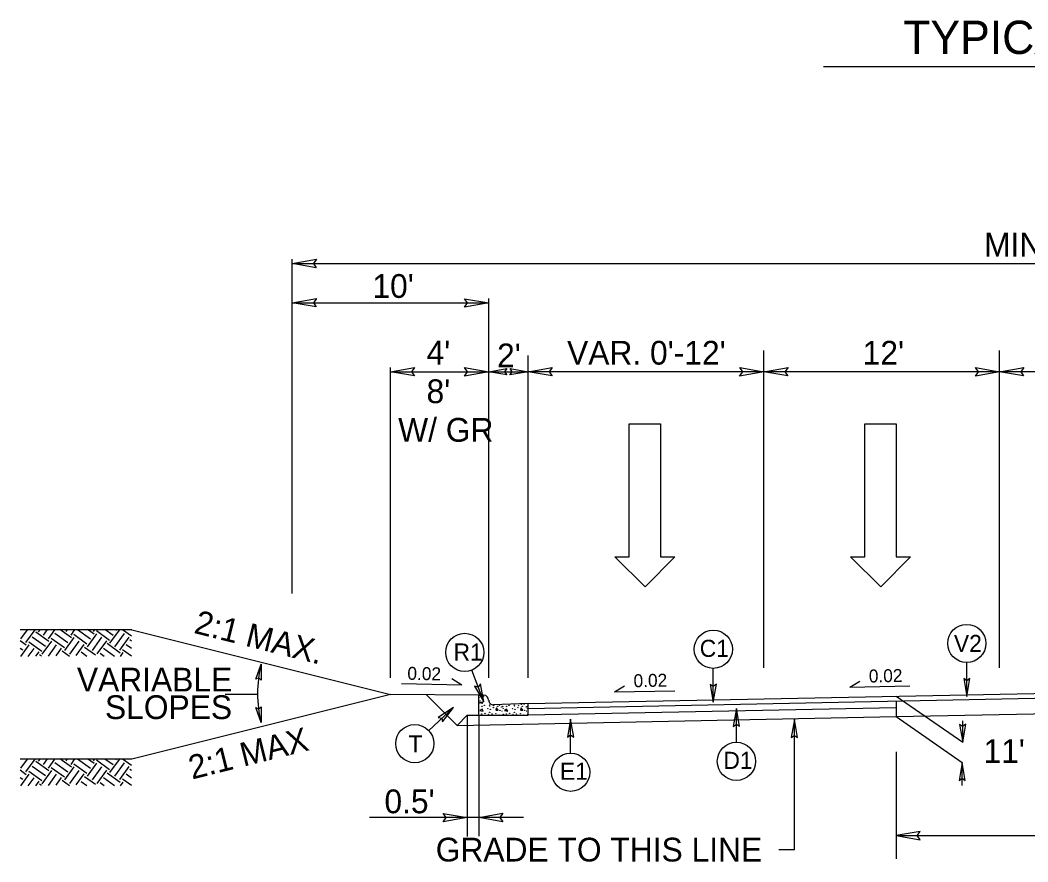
# Model space of a CAD drawing. Extents: x 3025871 to 3026431, y 707165 to 707825.
# Drawn here: x 3026115.5 to 3026166.8, y 707641 to 707683.9 of the extents above; entities that cross this region are included whole.
import ezdxf

# ---------------------------------------------------------------- set-up
doc = ezdxf.new("R2010")
doc.units = 0
for name, color, linetype in [('Prop Drainage Structure Junction Box with Manhole CELL', 7, 'Continuous'), ('Prop Drainage Structure Junction Box with Slab Lid TB 840 34 CELL', 7, 'Continuous'), ('Prop Drainage Structure Plot Symbol 50 Scale', 7, 'Continuous'), ('Prop Pavement Schedule Description CELL', 7, 'Continuous'), ('Sheet Data Field CELL', 7, 'Continuous'), ('Sheet Plot Border Inside CELL', 7, 'Continuous'), ('Sheet Sticker Incomplete CELL', 7, 'Continuous'), ('Sheet Typical CELL', 7, 'Continuous'), ('Typical Arrow Superelevation CELL', 7, 'Continuous'), ('Typical Grade Point Symbol CELL', 7, 'Continuous'), ('Typical Text Centerline CELL', 7, 'Continuous'), ('Typical Text Grade Point CELL', 7, 'Continuous')]:
    doc.layers.add(name, color=color, linetype=linetype)

msp = doc.modelspace()

# ---------------------------------------------------------------- linework, layer by layer
at = {"layer": 'Prop Drainage Structure Junction Box with Manhole CELL'}
msp.add_line((3026137.701, 707647.974), (3026160.043, 707648.421), dxfattribs=at)
at = {"layer": 'Prop Drainage Structure Junction Box with Slab Lid TB 840 34 CELL'}
for p, q in [((3026156.341, 707681.503), (3026191.781, 707681.503)), ((3026129.305, 707654.691), (3026129.305, 707671.691)), ((3026129.305, 707671.473), (3026223.819, 707671.473)), ((3026129.305, 707669.473), (3026139.305, 707669.473)), ((3026139.305, 707650.399), (3026139.305, 707669.691)), ((3026153.311, 707650.898), (3026153.311, 707667.04)), ((3026165.311, 707650.898), (3026165.311, 707667.04)), ((3026141.311, 707650.658), (3026141.311, 707666.8)), ((3026134.305, 707650.399), (3026134.305, 707666.185)), ((3026134.305, 707665.967), (3026139.305, 707665.967)), ((3026139.305, 707665.967), (3026141.311, 707665.967)), ((3026162.061, 707665.967), (3026141.311, 707665.967)), ((3026174.061, 707665.967), (3026153.311, 707665.967)), ((3026141.311, 707650.399), (3026141.311, 707665.704)), ((3026127.541, 707649.55), (3026125.885, 707649.55)), ((3026160.047, 707649.462), (3026163.433, 707647.114)), ((3026138.218, 707648.49), (3026138.218, 707642.327)), ((3026138.803, 707648.502), (3026138.803, 707642.339)), ((3026160.043, 707648.421), (3026163.41, 707646.085)), ((3026163.433, 707647.114), (3026163.433, 707648.206)), ((3026160.043, 707646.63), (3026160.043, 707641.192)), ((3026141.073, 707643.282), (3026133.231, 707643.282)), ((3026160.043, 707642.363), (3026187.799, 707642.363)), ((3026154.877, 707641.638), (3026154.067, 707641.638))]:
    msp.add_line(p, q, dxfattribs=at)
msp.add_arc((3026133.656, 707649.599), 6.116, 165.9638, 194.0362, dxfattribs=at)
at = {"layer": 'Prop Drainage Structure Plot Symbol 50 Scale'}
for p, q in [((3026138.803, 707648.502), (3026138.803, 707649.506)), ((3026138.803, 707649.506), (3026139.064, 707649.506)), ((3026138.839, 707649.126), (3026138.994, 707649.171)), ((3026138.977, 707649.08), (3026138.839, 707649.126)), ((3026138.994, 707649.171), (3026138.977, 707649.08)), ((3026139.304, 707649.255), (3026139.304, 707649.265)), ((3026141.311, 707649.088), (3026139.555, 707649.015)), ((3026141.311, 707648.502), (3026141.311, 707649.088)), ((3026138.803, 707648.502), (3026141.311, 707648.502)), ((3026138.966, 707648.807), (3026138.862, 707648.731)), ((3026138.862, 707648.731), (3026139.028, 707648.692)), ((3026139.028, 707648.692), (3026138.966, 707648.807)), ((3026139.71, 707648.863), (3026139.675, 707648.749)), ((3026139.675, 707648.749), (3026139.796, 707648.743)), ((3026139.796, 707648.743), (3026139.71, 707648.863)), ((3026140.219, 707648.807), (3026140.115, 707648.731)), ((3026140.115, 707648.731), (3026140.282, 707648.692)), ((3026140.282, 707648.692), (3026140.219, 707648.807)), ((3026140.963, 707648.863), (3026140.929, 707648.749)), ((3026140.929, 707648.749), (3026141.05, 707648.743)), ((3026141.05, 707648.743), (3026140.963, 707648.863))]:
    msp.add_line(p, q, dxfattribs=at)
for centre in [(3026138.816, 707649.395), (3026138.868, 707649.212), (3026139.034, 707649.43), (3026139.085, 707648.989), (3026139.343, 707649.017), (3026139.36, 707648.967), (3026139.567, 707648.983), (3026139.859, 707648.987), (3026140.339, 707648.989), (3026140.597, 707649.017), (3026140.614, 707648.967), (3026140.82, 707648.983), (3026140.969, 707649.046), (3026141.112, 707649.029), (3026138.948, 707648.548), (3026138.965, 707648.938), (3026139.12, 707648.589), (3026139.263, 707648.823), (3026139.297, 707648.526), (3026139.355, 707648.64), (3026139.389, 707648.795), (3026139.469, 707648.554), (3026139.538, 707648.881), (3026139.675, 707648.577), (3026139.761, 707648.944), (3026139.836, 707648.508), (3026139.887, 707648.743), (3026139.968, 707648.904), (3026139.984, 707648.697), (3026140.024, 707648.938), (3026140.041, 707648.841), (3026140.047, 707648.531), (3026140.201, 707648.548), (3026140.219, 707648.938), (3026140.373, 707648.589), (3026140.516, 707648.823), (3026140.551, 707648.526), (3026140.608, 707648.64), (3026140.643, 707648.795), (3026140.723, 707648.554), (3026140.792, 707648.881), (3026140.929, 707648.577), (3026141.015, 707648.944), (3026141.089, 707648.508), (3026141.141, 707648.743), (3026141.221, 707648.904), (3026141.237, 707648.697), (3026141.278, 707648.938), (3026141.295, 707648.841), (3026141.3, 707648.531)]:
    msp.add_circle(centre, 0.00805, dxfattribs=at)
for centre, start, end in [((3026139.064, 707649.265), 0, 90), ((3026139.545, 707649.255), 180, 272.3845)]:
    msp.add_arc(centre, 0.24, start, end, dxfattribs=at)
at = {"layer": 'Prop Pavement Schedule Description CELL'}
for p, q in [((3026141.311, 707649.088), (3026174.061, 707649.743)), ((3026141.311, 707648.838), (3026174.061, 707649.493)), ((3026160.047, 707649.212), (3026160.043, 707648.421)), ((3026141.311, 707648.504), (3026160.045, 707648.879)), ((3026160.043, 707648.421), (3026174.081, 707648.701))]:
    msp.add_line(p, q, dxfattribs=at)
at = {"layer": 'Sheet Data Field CELL'}
for p, q in [((3026146.453, 707656.551), (3026146.453, 707663.321)), ((3026146.453, 707663.321), (3026148.049, 707663.321)), ((3026148.049, 707663.321), (3026148.049, 707656.551)), ((3026158.453, 707656.551), (3026158.453, 707663.321)), ((3026158.453, 707663.321), (3026160.049, 707663.321)), ((3026160.049, 707663.321), (3026160.049, 707656.551)), ((3026147.275, 707655.028), (3026145.728, 707656.551)), ((3026145.728, 707656.551), (3026146.453, 707656.551)), ((3026148.774, 707656.551), (3026147.275, 707655.028)), ((3026148.049, 707656.551), (3026148.774, 707656.551)), ((3026159.275, 707655.028), (3026157.728, 707656.551)), ((3026157.728, 707656.551), (3026158.453, 707656.551)), ((3026160.774, 707656.551), (3026159.275, 707655.028)), ((3026160.049, 707656.551), (3026160.774, 707656.551))]:
    msp.add_line(p, q, dxfattribs=at)
at = {"layer": 'Sheet Plot Border Inside CELL'}
msp.add_line((3026138.218, 707648.49), (3026138.803, 707648.502), dxfattribs=at)
at = {"layer": 'Sheet Sticker Incomplete CELL'}
for p, q in [((3026137.942, 707650.027), (3026134.874, 707650.084)), ((3026137.942, 707650.027), (3026137.426, 707650.338)), ((3026145.705, 707649.678), (3026146.22, 707649.99)), ((3026157.682, 707649.918), (3026158.197, 707650.229)), ((3026157.682, 707649.918), (3026160.75, 707649.979)), ((3026145.705, 707649.678), (3026148.773, 707649.74))]:
    msp.add_line(p, q, dxfattribs=at)
at = {"layer": 'Sheet Typical CELL'}
for p, q in [((3026138.803, 707649.506), (3026134.305, 707649.55)), ((3026137.701, 707647.974), (3026136.143, 707649.532)), ((3026138.218, 707648.49), (3026137.701, 707647.974))]:
    msp.add_line(p, q, dxfattribs=at)
at = {"layer": 'Typical Grade Point Symbol CELL'}
for p, q in [((3026163.643, 707649.446), (3026163.642, 707651.17)), ((3026139.065, 707649.173), (3026138.441, 707650.781)), ((3026150.74, 707649.151), (3026150.739, 707650.875)), ((3026136.254, 707647.709), (3026137.511, 707648.889)), ((3026151.916, 707647.115), (3026151.915, 707648.839)), ((3026143.477, 707646.562), (3026143.476, 707648.287)), ((3026154.877, 707641.638), (3026154.873, 707648.265)), ((3026163.411, 707644.913), (3026163.41, 707646.085))]:
    msp.add_line(p, q, dxfattribs=at)
for centre in [(3026163.642, 707652.142), (3026138.09, 707651.687), (3026150.739, 707651.847), (3026135.544, 707647.045), (3026151.916, 707646.143), (3026143.477, 707645.59)]:
    msp.add_circle(centre, 0.972, dxfattribs=at)
at = {"layer": 'Typical Text Centerline CELL'}
for points in [[(3026130.53, 707671.262), (3026129.305, 707671.473), (3026130.537, 707671.691), (3026130.381, 707671.473)], [(3026130.53, 707669.262), (3026129.305, 707669.473), (3026130.537, 707669.691), (3026130.381, 707669.473)], [(3026138.08, 707669.684), (3026139.305, 707669.473), (3026138.073, 707669.255), (3026138.23, 707669.473)], [(3026135.53, 707665.756), (3026134.305, 707665.967), (3026135.537, 707666.185), (3026135.381, 707665.967)], [(3026138.08, 707666.178), (3026139.305, 707665.967), (3026138.073, 707665.75), (3026138.23, 707665.967)], [(3026140.223, 707665.809), (3026139.305, 707665.967), (3026140.229, 707666.131), (3026140.111, 707665.967)], [(3026140.394, 707666.126), (3026141.313, 707665.967), (3026140.389, 707665.804), (3026140.507, 707665.967)], [(3026142.536, 707665.756), (3026141.311, 707665.967), (3026142.543, 707666.185), (3026142.387, 707665.967)], [(3026152.086, 707666.178), (3026153.311, 707665.967), (3026152.079, 707665.749), (3026152.236, 707665.967)], [(3026154.536, 707665.756), (3026153.311, 707665.967), (3026154.543, 707666.185), (3026154.387, 707665.967)], [(3026164.086, 707666.178), (3026165.311, 707665.967), (3026164.079, 707665.749), (3026164.236, 707665.967)], [(3026166.536, 707665.756), (3026165.311, 707665.967), (3026166.543, 707666.185), (3026166.387, 707665.967)], [(3026127.458, 707650.326), (3026127.723, 707651.082), (3026127.73, 707650.276), (3026127.608, 707650.398)], [(3026138.59, 707649.965), (3026139.065, 707649.173), (3026138.885, 707650.084), (3026138.776, 707649.918)], [(3026150.583, 707650.06), (3026150.74, 707649.151), (3026150.902, 707650.066), (3026150.74, 707649.949)], [(3026163.486, 707650.355), (3026163.643, 707649.446), (3026163.804, 707650.36), (3026163.642, 707650.244)], [(3026127.725, 707648.917), (3026127.723, 707648.116), (3026127.452, 707648.876), (3026127.607, 707648.8)], [(3026136.955, 707648.153), (3026137.511, 707648.889), (3026136.734, 707648.381), (3026136.929, 707648.343)], [(3026152.072, 707647.93), (3026151.915, 707648.839), (3026151.754, 707647.925), (3026151.916, 707648.041)], [(3026143.634, 707647.377), (3026143.476, 707648.287), (3026143.315, 707647.372), (3026143.477, 707647.488)], [(3026155.03, 707647.355), (3026154.873, 707648.265), (3026154.711, 707647.35), (3026154.873, 707647.466)], [(3026163.276, 707648.023), (3026163.433, 707647.114), (3026163.594, 707648.029), (3026163.432, 707647.912)], [(3026163.567, 707645.175), (3026163.41, 707646.085), (3026163.249, 707645.17), (3026163.41, 707645.286)], [(3026136.993, 707643.493), (3026138.218, 707643.282), (3026136.986, 707643.065), (3026137.143, 707643.282)], [(3026140.028, 707643.071), (3026138.803, 707643.282), (3026140.034, 707643.5), (3026139.878, 707643.282)], [(3026161.268, 707642.574), (3026160.043, 707642.363), (3026161.275, 707642.145), (3026161.118, 707642.363)]]:
    msp.add_lwpolyline(points, close=True, dxfattribs=at)
at = {"layer": 'Typical Text Grade Point CELL'}
for p, q in [((3026121.14, 707652.841), (3026115.456, 707652.841)), ((3026121.14, 707652.841), (3026115.456, 707652.841)), ((3026115.496, 707652.371), (3026115.834, 707652.841)), ((3026115.496, 707652.371), (3026115.834, 707652.841)), ((3026115.746, 707652.191), (3026116.214, 707652.841)), ((3026115.746, 707652.191), (3026116.214, 707652.841)), ((3026116.919, 707652.236), (3026116.25, 707652.716)), ((3026116.919, 707652.236), (3026116.25, 707652.716)), ((3026116.394, 707652.74), (3026116.467, 707652.841)), ((3026116.394, 707652.74), (3026116.467, 707652.841)), ((3026116.645, 707652.56), (3026116.856, 707652.853)), ((3026116.645, 707652.56), (3026116.856, 707652.853)), ((3026116.895, 707652.379), (3026117.227, 707652.841)), ((3026116.895, 707652.379), (3026117.227, 707652.841)), ((3026117.887, 707652.173), (3026117.219, 707652.654)), ((3026117.887, 707652.173), (3026117.219, 707652.654)), ((3026118.067, 707652.424), (3026117.472, 707652.851)), ((3026118.067, 707652.424), (3026117.472, 707652.851)), ((3026117.793, 707652.748), (3026117.867, 707652.85)), ((3026117.793, 707652.748), (3026117.867, 707652.85)), ((3026118.044, 707652.567), (3026118.246, 707652.849)), ((3026118.044, 707652.567), (3026118.246, 707652.849)), ((3026118.856, 707652.111), (3026118.188, 707652.591)), ((3026118.856, 707652.111), (3026118.188, 707652.591)), ((3026119.036, 707652.361), (3026118.368, 707652.842)), ((3026119.036, 707652.361), (3026118.368, 707652.842)), ((3026118.879, 707651.967), (3026119.36, 707652.635)), ((3026118.879, 707651.967), (3026119.36, 707652.635)), ((3026119.216, 707652.612), (3026118.889, 707652.847)), ((3026119.216, 707652.612), (3026118.889, 707652.847)), ((3026119.193, 707652.756), (3026119.258, 707652.846)), ((3026119.193, 707652.756), (3026119.258, 707652.846)), ((3026120.005, 707652.299), (3026119.336, 707652.779)), ((3026120.005, 707652.299), (3026119.336, 707652.779)), ((3026120.185, 707652.549), (3026119.774, 707652.845)), ((3026120.185, 707652.549), (3026119.774, 707652.845)), ((3026120.028, 707652.155), (3026120.508, 707652.824)), ((3026120.028, 707652.155), (3026120.508, 707652.824)), ((3026120.279, 707651.975), (3026120.759, 707652.643)), ((3026120.279, 707651.975), (3026120.759, 707652.643)), ((3026120.365, 707652.8), (3026120.305, 707652.843)), ((3026120.365, 707652.8), (3026120.305, 707652.843)), ((3026121.118, 707652.512), (3026120.659, 707652.842)), ((3026121.118, 707652.512), (3026120.659, 707652.842)), ((3026121.14, 707652.841), (3026134.305, 707649.55)), ((3026115.77, 707652.048), (3026115.456, 707652.274)), ((3026115.77, 707652.048), (3026115.456, 707652.274)), ((3026115.484, 707651.473), (3026115.914, 707652.071)), ((3026115.484, 707651.473), (3026115.914, 707652.071)), ((3026116.558, 707651.735), (3026115.89, 707652.215)), ((3026116.558, 707651.735), (3026115.89, 707652.215)), ((3026116.739, 707651.985), (3026116.07, 707652.465)), ((3026116.739, 707651.985), (3026116.07, 707652.465)), ((3026116.582, 707651.591), (3026117.062, 707652.259)), ((3026116.582, 707651.591), (3026117.062, 707652.259)), ((3026116.898, 707651.501), (3026117.313, 707652.079)), ((3026116.898, 707651.501), (3026117.313, 707652.079)), ((3026117.707, 707651.923), (3026117.039, 707652.403)), ((3026117.707, 707651.923), (3026117.039, 707652.403)), ((3026117.731, 707651.779), (3026118.211, 707652.447)), ((3026117.731, 707651.779), (3026118.211, 707652.447)), ((3026117.981, 707651.599), (3026118.462, 707652.267)), ((3026117.981, 707651.599), (3026118.462, 707652.267)), ((3026118.312, 707651.53), (3026118.712, 707652.087)), ((3026118.312, 707651.53), (3026118.712, 707652.087)), ((3026119.13, 707651.787), (3026119.61, 707652.455)), ((3026119.13, 707651.787), (3026119.61, 707652.455)), ((3026119.381, 707651.607), (3026119.861, 707652.275)), ((3026119.381, 707651.607), (3026119.861, 707652.275)), ((3026120.553, 707651.651), (3026119.885, 707652.132)), ((3026120.553, 707651.651), (3026119.885, 707652.132)), ((3026120.529, 707651.795), (3026121.01, 707652.463)), ((3026120.529, 707651.795), (3026121.01, 707652.463)), ((3026121.118, 707651.878), (3026120.853, 707652.069)), ((3026121.118, 707651.878), (3026120.853, 707652.069)), ((3026121.118, 707652.259), (3026121.033, 707652.32)), ((3026121.118, 707652.259), (3026121.033, 707652.32)), ((3026115.59, 707651.797), (3026115.456, 707651.894)), ((3026115.59, 707651.797), (3026115.456, 707651.894)), ((3026115.869, 707651.481), (3026116.164, 707651.891)), ((3026115.869, 707651.481), (3026116.164, 707651.891)), ((3026116.255, 707651.488), (3026116.415, 707651.711)), ((3026116.255, 707651.488), (3026116.415, 707651.711)), ((3026116.541, 707651.494), (3026116.438, 707651.567)), ((3026116.541, 707651.494), (3026116.438, 707651.567)), ((3026117.283, 707651.509), (3026117.564, 707651.899)), ((3026117.283, 707651.509), (3026117.564, 707651.899)), ((3026117.969, 707651.481), (3026117.587, 707651.755)), ((3026117.969, 707651.481), (3026117.587, 707651.755)), ((3026118.85, 707651.481), (3026118.556, 707651.693)), ((3026118.85, 707651.481), (3026118.556, 707651.693)), ((3026119.285, 707651.549), (3026118.736, 707651.944)), ((3026119.285, 707651.549), (3026118.736, 707651.944)), ((3026119.732, 707651.481), (3026119.524, 707651.63)), ((3026119.732, 707651.481), (3026119.524, 707651.63)), ((3026120.261, 707651.481), (3026119.704, 707651.881)), ((3026120.261, 707651.481), (3026119.704, 707651.881)), ((3026120.557, 707651.481), (3026120.697, 707651.675)), ((3026120.557, 707651.481), (3026120.697, 707651.675)), ((3026121.118, 707651.498), (3026120.673, 707651.818)), ((3026121.118, 707651.498), (3026120.673, 707651.818)), ((3026134.305, 707649.55), (3026121.14, 707646.259)), ((3026121.14, 707646.259), (3026115.456, 707646.259)), ((3026121.14, 707646.259), (3026115.456, 707646.259)), ((3026115.496, 707645.789), (3026115.834, 707646.259)), ((3026115.496, 707645.789), (3026115.834, 707646.259)), ((3026115.746, 707645.609), (3026116.214, 707646.259)), ((3026115.746, 707645.609), (3026116.214, 707646.259)), ((3026116.739, 707645.403), (3026116.07, 707645.883)), ((3026116.739, 707645.403), (3026116.07, 707645.883)), ((3026116.919, 707645.653), (3026116.25, 707646.134)), ((3026116.919, 707645.653), (3026116.25, 707646.134)), ((3026116.394, 707646.157), (3026116.467, 707646.259)), ((3026116.394, 707646.157), (3026116.467, 707646.259)), ((3026116.645, 707645.977), (3026116.856, 707646.271)), ((3026116.645, 707645.977), (3026116.856, 707646.271)), ((3026116.895, 707645.797), (3026117.227, 707646.259)), ((3026116.895, 707645.797), (3026117.227, 707646.259)), ((3026117.887, 707645.591), (3026117.219, 707646.071)), ((3026117.887, 707645.591), (3026117.219, 707646.071)), ((3026118.067, 707645.841), (3026117.472, 707646.269)), ((3026118.067, 707645.841), (3026117.472, 707646.269)), ((3026117.793, 707646.165), (3026117.867, 707646.268)), ((3026117.793, 707646.165), (3026117.867, 707646.268)), ((3026118.044, 707645.985), (3026118.246, 707646.267)), ((3026118.044, 707645.985), (3026118.246, 707646.267)), ((3026118.856, 707645.528), (3026118.188, 707646.008)), ((3026118.856, 707645.528), (3026118.188, 707646.008)), ((3026119.036, 707645.779), (3026118.368, 707646.259)), ((3026119.036, 707645.779), (3026118.368, 707646.259)), ((3026118.879, 707645.384), (3026119.36, 707646.053)), ((3026118.879, 707645.384), (3026119.36, 707646.053)), ((3026119.216, 707646.029), (3026118.889, 707646.265)), ((3026119.216, 707646.029), (3026118.889, 707646.265)), ((3026119.193, 707646.173), (3026119.258, 707646.264)), ((3026119.193, 707646.173), (3026119.258, 707646.264)), ((3026120.005, 707645.716), (3026119.336, 707646.196)), ((3026120.005, 707645.716), (3026119.336, 707646.196)), ((3026120.185, 707645.967), (3026119.774, 707646.262)), ((3026120.185, 707645.967), (3026119.774, 707646.262)), ((3026120.028, 707645.573), (3026120.508, 707646.241)), ((3026120.028, 707645.573), (3026120.508, 707646.241)), ((3026120.279, 707645.392), (3026120.759, 707646.061)), ((3026120.279, 707645.392), (3026120.759, 707646.061)), ((3026120.365, 707646.217), (3026120.305, 707646.261)), ((3026120.365, 707646.217), (3026120.305, 707646.261)), ((3026120.529, 707645.212), (3026121.01, 707645.881)), ((3026120.529, 707645.212), (3026121.01, 707645.881)), ((3026121.118, 707645.929), (3026120.659, 707646.26)), ((3026121.118, 707645.929), (3026120.659, 707646.26)), ((3026115.77, 707645.465), (3026115.456, 707645.691)), ((3026115.77, 707645.465), (3026115.456, 707645.691)), ((3026115.484, 707644.89), (3026115.914, 707645.489)), ((3026115.484, 707644.89), (3026115.914, 707645.489)), ((3026116.558, 707645.152), (3026115.89, 707645.632)), ((3026116.558, 707645.152), (3026115.89, 707645.632)), ((3026116.582, 707645.008), (3026117.062, 707645.677)), ((3026116.582, 707645.008), (3026117.062, 707645.677)), ((3026116.898, 707644.919), (3026117.313, 707645.497)), ((3026116.898, 707644.919), (3026117.313, 707645.497)), ((3026117.707, 707645.34), (3026117.039, 707645.82)), ((3026117.707, 707645.34), (3026117.039, 707645.82)), ((3026117.731, 707645.196), (3026118.211, 707645.865)), ((3026117.731, 707645.196), (3026118.211, 707645.865)), ((3026117.981, 707645.016), (3026118.462, 707645.685)), ((3026117.981, 707645.016), (3026118.462, 707645.685)), ((3026118.312, 707644.947), (3026118.712, 707645.505)), ((3026118.312, 707644.947), (3026118.712, 707645.505)), ((3026119.13, 707645.204), (3026119.61, 707645.873)), ((3026119.13, 707645.204), (3026119.61, 707645.873)), ((3026119.381, 707645.024), (3026119.861, 707645.693)), ((3026119.381, 707645.024), (3026119.861, 707645.693)), ((3026120.553, 707645.069), (3026119.885, 707645.549)), ((3026120.553, 707645.069), (3026119.885, 707645.549)), ((3026121.118, 707645.296), (3026120.853, 707645.486)), ((3026121.118, 707645.296), (3026120.853, 707645.486)), ((3026121.118, 707645.676), (3026121.033, 707645.737)), ((3026121.118, 707645.676), (3026121.033, 707645.737)), ((3026115.59, 707645.215), (3026115.456, 707645.311)), ((3026115.59, 707645.215), (3026115.456, 707645.311)), ((3026115.869, 707644.898), (3026116.164, 707645.309)), ((3026115.869, 707644.898), (3026116.164, 707645.309)), ((3026116.255, 707644.906), (3026116.415, 707645.128)), ((3026116.255, 707644.906), (3026116.415, 707645.128)), ((3026116.541, 707644.911), (3026116.438, 707644.985)), ((3026116.541, 707644.911), (3026116.438, 707644.985)), ((3026117.283, 707644.926), (3026117.564, 707645.316)), ((3026117.283, 707644.926), (3026117.564, 707645.316)), ((3026117.969, 707644.899), (3026117.587, 707645.173)), ((3026117.969, 707644.899), (3026117.587, 707645.173)), ((3026118.85, 707644.899), (3026118.556, 707645.11)), ((3026118.85, 707644.899), (3026118.556, 707645.11)), ((3026119.285, 707644.966), (3026118.736, 707645.361)), ((3026119.285, 707644.966), (3026118.736, 707645.361)), ((3026119.732, 707644.899), (3026119.524, 707645.048)), ((3026119.732, 707644.899), (3026119.524, 707645.048)), ((3026120.261, 707644.899), (3026119.704, 707645.298)), ((3026120.261, 707644.899), (3026119.704, 707645.298)), ((3026120.557, 707644.899), (3026120.697, 707645.092)), ((3026120.557, 707644.899), (3026120.697, 707645.092)), ((3026121.118, 707644.916), (3026120.673, 707645.236)), ((3026121.118, 707644.916), (3026120.673, 707645.236))]:
    msp.add_line(p, q, dxfattribs=at)

# ---------------------------------------------------------------- texts
at = {"layer": 'Prop Drainage Structure Junction Box with Slab Lid TB 840 34 CELL'}
msp.add_text('TYPICAL SECTION NO. 1 ', height=1.69489, rotation=360, dxfattribs=at).set_placement((3026160.406, 707682.136))
for s, height, p in [('MINIMUM ROW WIDTH', 1.20892, (3026164.522, 707671.829)), ("10'", 1.2089, (3026133.387, 707669.726)), ("4'", 1.2089, (3026136.143, 707666.335)), ("2'", 1.2089, (3026139.732, 707666.193)), ("VAR. 0'-12'", 1.20892, (3026143.296, 707666.329)), ("12'", 1.2089, (3026158.344, 707666.329)), ("8'", 1.2089, (3026136.143, 707664.37)), ('W/ GR', 1.2089, (3026134.699, 707662.406)), ("11'", 1.2089, (3026164.491, 707646.06)), ("0.5'", 1.2089, (3026133.999, 707643.503)), ('GRADE TO THIS LINE', 1.20892, (3026136.61, 707641.048))]:
    msp.add_text(s, height=height, dxfattribs=at).set_placement(p)
at = {"layer": 'Sheet Sticker Incomplete CELL'}
for s, rotation, p in [('0.02', 358.9408, (3026135.162, 707650.296)), ('0.02 ', 1.2029, (3026146.686, 707649.914)), ('0.02 ', 1.2029, (3026158.662, 707650.153))]:
    msp.add_text(s, height=0.6583, rotation=rotation, dxfattribs=at).set_placement(p)
at = {"layer": 'Typical Arrow Superelevation CELL'}
for s, p in [('V2', (3026162.987, 707651.707)), ('C1', (3026150.047, 707651.459)), ('D1', (3026151.253, 707645.76)), ('E1', (3026142.932, 707645.207))]:
    msp.add_text(s, height=0.87, dxfattribs=at).set_placement(p)
for s, p in [('R1', (3026137.516, 707651.271)), ('T', (3026135.223, 707646.597))]:
    msp.add_text(s, height=0.87, rotation=360, dxfattribs=at).set_placement(p)
at = {"layer": 'Typical Text Grade Point CELL'}
for s, rotation, p in [('2:1 MAX.', 345.9638, (3026124.251, 707652.682)), ('2:1 MAX', 14.0362, (3026124.205, 707645.218))]:
    msp.add_text(s, height=1.2089, rotation=rotation, dxfattribs=at).set_placement(p)
for s, p in [('VARIABLE', (3026118.345, 707649.698)), ('SLOPES', (3026119.774, 707648.296))]:
    msp.add_text(s, height=1.2089, dxfattribs=at).set_placement(p)

doc.saveas('drawing.dxf')
